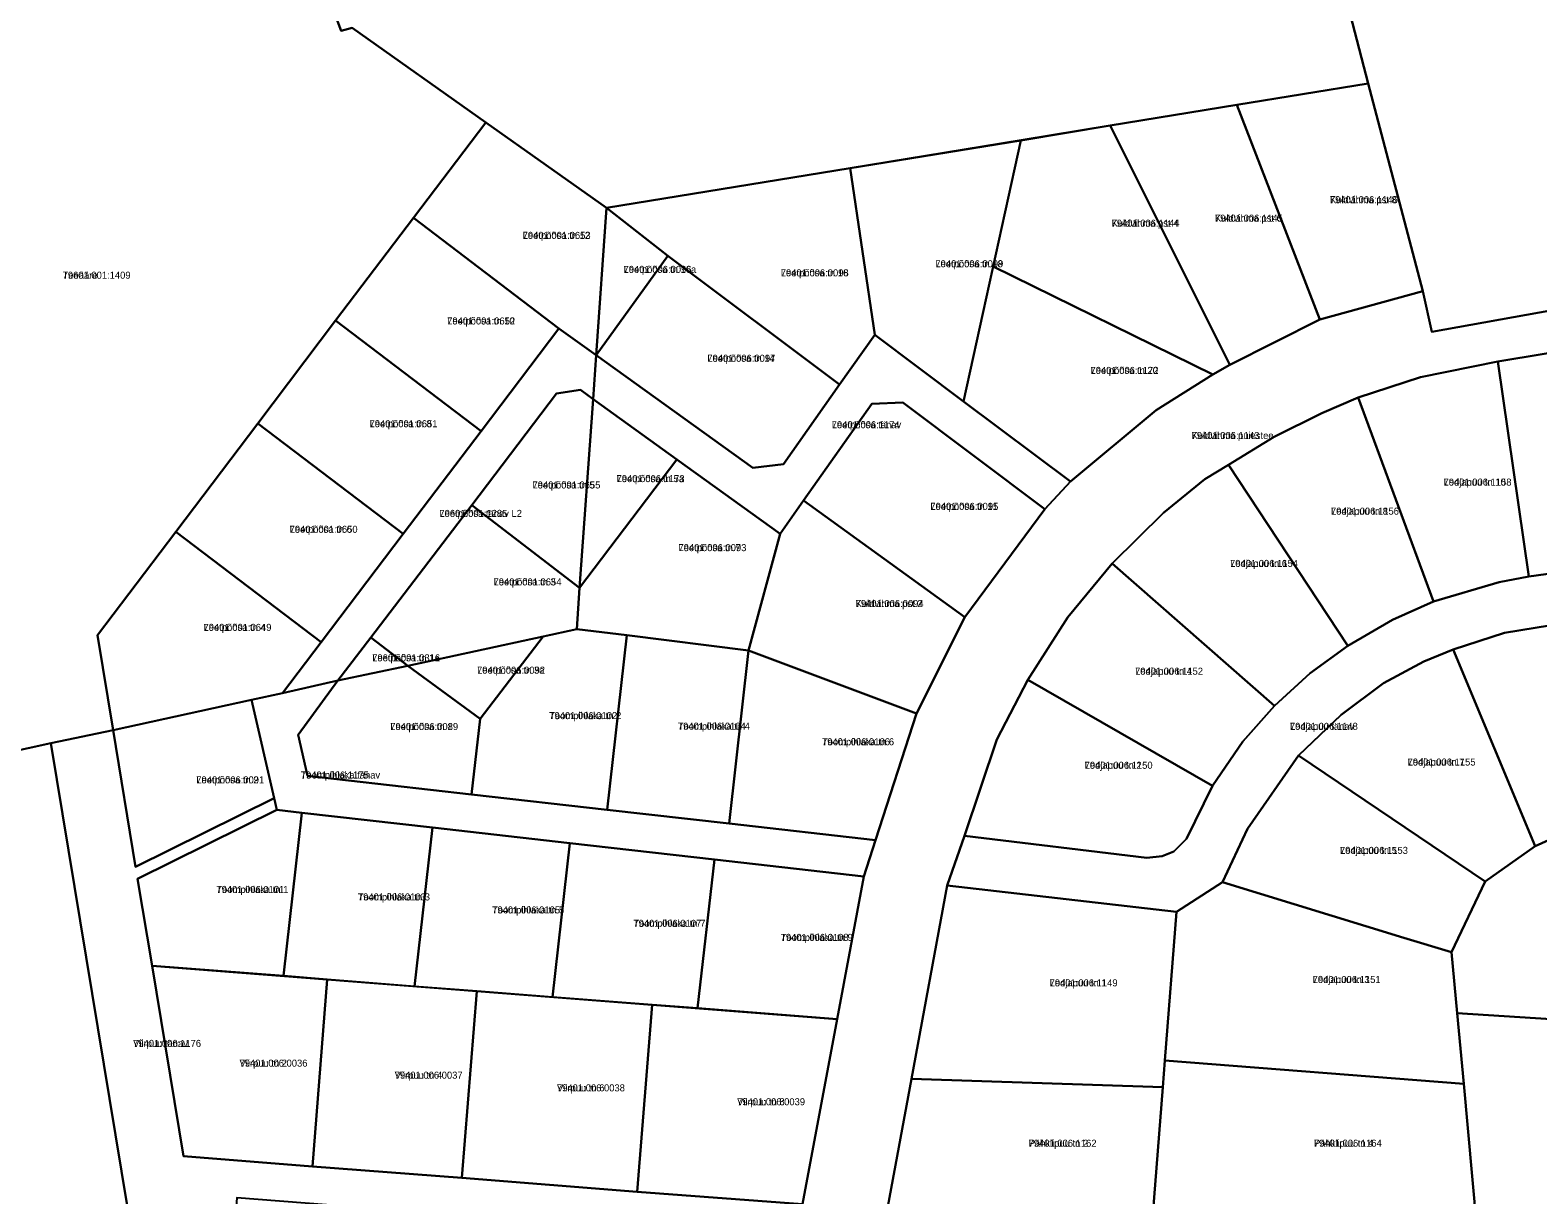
# Model space of a CAD drawing. Extents: x 625111 to 706696, y 6474150 to 6504223.
# Drawn here: x 658379.2 to 658701.1, y 6477286.7 to 6477535.3 of the extents above; entities that cross this region are included whole.
import ezdxf

# ---------------------------------------------------------------- set-up
doc = ezdxf.new("R2010")
doc.units = 0
for name, color, linetype in [('L_AADRESS', 7, 'Continuous'), ('PIIR', 7, 'Continuous'), ('TUNNUS', 7, 'Continuous')]:
    doc.layers.add(name, color=color, linetype=linetype)

msp = doc.modelspace()

# ---------------------------------------------------------------- linework, layer by layer
at = {"layer": 'PIIR'}
for points in [[(658807.19, 6477493.92), (658767, 6477486.74), (658756.55, 6477484.86), (658727.2, 6477479.64), (658678.44, 6477470.94), (658676.54, 6477479.6), (658664.87, 6477523.91), (658625, 6477677.45), (658727.35, 6477707.93), (658827.16, 6477726.6), (658855.42, 6477705.99), (658921.35, 6477514.3), (658868.14, 6477504.79)], [(658664.87, 6477523.91), (658636.85, 6477519.38), (658609.75, 6477514.92), (658590.75, 6477511.83), (658554.26, 6477505.84), (658502.28, 6477497.39), (658476.47, 6477515.58), (658447.92, 6477535.78), (658445.6, 6477535.16), (658420.4, 6477602.12), (658422.48, 6477603), (658480.42, 6477633.97), (658625, 6477677.45)], [(658295.81, 6477363.77), (658298.99, 6477419.35), (658308.47, 6477456.27), (658317.08, 6477478.52), (658327.48, 6477502.41), (658338.32, 6477525.23), (658352.68, 6477544.97), (658370, 6477564.62), (658397.69, 6477592.48), (658420.4, 6477602.12), (658445.6, 6477535.16), (658447.92, 6477535.78), (658476.47, 6477515.58), (658461.03, 6477495.21), (658444.4, 6477473.3), (658427.82, 6477451.36), (658410.32, 6477428.26), (658393.57, 6477406.17), (658396.9, 6477385.91), (658383.6, 6477383.09)], [(658664.87, 6477523.91), (658676.54, 6477479.6), (658654.55, 6477473.55), (658636.85, 6477519.38)], [(658636.85, 6477519.38), (658654.55, 6477473.55), (658635.36, 6477463.84), (658609.75, 6477514.92)], [(658461.03, 6477495.21), (658476.47, 6477515.58), (658502.28, 6477497.39), (658500.06, 6477465.93), (658492.1, 6477471.64)], [(658609.75, 6477514.92), (658635.36, 6477463.84), (658631.68, 6477461.79), (658584.8, 6477484.87), (658590.68, 6477511.77)], [(658590.68, 6477511.77), (658578.48, 6477456.07), (658559.52, 6477470.29), (658554.26, 6477505.84)], [(658554.26, 6477505.84), (658559.52, 6477470.29), (658552.02, 6477459.66), (658515.36, 6477487.16), (658502.28, 6477497.39)], [(658502.28, 6477497.39), (658515.36, 6477487.16), (658500.06, 6477465.93)], [(658475.53, 6477449.74), (658444.4, 6477473.3), (658461.03, 6477495.21), (658492.1, 6477471.64)], [(658515.36, 6477487.16), (658552.02, 6477459.66), (658540.01, 6477442.64), (658533.47, 6477441.87), (658500.06, 6477465.93)], [(658584.8, 6477484.87), (658631.68, 6477461.79), (658619.61, 6477454.18), (658601.29, 6477438.98), (658578.48, 6477456.07)], [(658458.87, 6477427.81), (658427.82, 6477451.36), (658444.4, 6477473.3), (658475.53, 6477449.74)], [(658475.53, 6477449.74), (658492.1, 6477471.64), (658500.06, 6477465.93), (658499.4, 6477456.55), (658496.67, 6477458.5), (658491.59, 6477457.72), (658473.5, 6477433.94), (658451.91, 6477405.64), (658444.92, 6477396.49), (658433.1, 6477393.78), (658441.34, 6477404.68), (658458.87, 6477427.81)], [(658500.06, 6477465.93), (658533.47, 6477441.87), (658540.01, 6477442.64), (658552.02, 6477459.66), (658559.52, 6477470.29), (658578.48, 6477456.07), (658601.29, 6477438.98), (658595.83, 6477433.06), (658565.51, 6477455.8), (658558.93, 6477455.56), (658544.34, 6477434.9), (658539.31, 6477427.79), (658517.3, 6477443.65), (658499.4, 6477456.55)], [(658725.54, 6477459.66), (658721.35, 6477419.53), (658713.41, 6477419.76), (658704.83, 6477419.45), (658699.16, 6477418.71), (658692.52, 6477464.58), (658712.34, 6477467.87), (658713.78, 6477458.02)], [(658692.52, 6477464.58), (658699.16, 6477418.71), (658692.8, 6477417.51), (658678.8, 6477413.33), (658662.76, 6477456.89), (658676.06, 6477461.21)], [(658473.5, 6477433.94), (658491.59, 6477457.72), (658496.67, 6477458.5), (658499.4, 6477456.55), (658496.52, 6477416.28)], [(658517.3, 6477443.65), (658496.52, 6477416.28), (658499.4, 6477456.55)], [(658565.51, 6477455.8), (658595.83, 6477433.06), (658578.77, 6477410.04), (658544.34, 6477434.9), (658558.93, 6477455.56)], [(658662.76, 6477456.89), (658678.8, 6477413.33), (658670.06, 6477409.44), (658660.54, 6477403.93), (658635.07, 6477442.52), (658644.77, 6477448.47), (658654.96, 6477453.55)], [(658441.34, 6477404.68), (658410.32, 6477428.26), (658427.82, 6477451.36), (658458.87, 6477427.81)], [(658517.3, 6477443.65), (658539.31, 6477427.79), (658532.6, 6477402.93), (658506.6, 6477406.15), (658495.93, 6477407.47), (658496.52, 6477416.28)], [(658635.07, 6477442.52), (658660.54, 6477403.93), (658652.51, 6477398.04), (658644.87, 6477391.12), (658610.22, 6477421.46), (658621.18, 6477432.3), (658630.02, 6477439.45)], [(658451.91, 6477405.64), (658473.5, 6477433.94), (658496.52, 6477416.28), (658495.93, 6477407.47), (658488.71, 6477405.9), (658459.87, 6477399.64)], [(658544.34, 6477434.9), (658578.77, 6477410.04), (658568.41, 6477389.45), (658532.6, 6477402.93), (658539.31, 6477427.79)], [(658396.9, 6477385.91), (658393.57, 6477406.17), (658410.32, 6477428.26), (658441.34, 6477404.68), (658433.1, 6477393.78), (658426.43, 6477392.36)], [(658610.22, 6477421.46), (658644.87, 6477391.12), (658638.1, 6477383.5), (658631.6, 6477373.99), (658592.18, 6477396.64), (658600.72, 6477409.98)], [(658495.93, 6477407.47), (658506.6, 6477406.15), (658502.38, 6477368.92), (658473.45, 6477372.2), (658475.28, 6477388.34), (658488.71, 6477405.9)], [(658720.05, 6477408.61), (658717.28, 6477368.65), (658700.53, 6477361.16), (658683.04, 6477403.08), (658693.96, 6477406.64), (658707.04, 6477408.8)], [(658459.87, 6477399.64), (658444.92, 6477396.49), (658451.91, 6477405.64)], [(658488.71, 6477405.9), (658475.28, 6477388.34), (658459.87, 6477399.64)], [(658506.6, 6477406.15), (658532.6, 6477402.93), (658528.41, 6477365.97), (658502.38, 6477368.92)], [(658532.6, 6477402.93), (658568.41, 6477389.45), (658559.69, 6477362.43), (658528.41, 6477365.97)], [(658683.04, 6477403.08), (658700.53, 6477361.16), (658689.81, 6477353.63), (658650.02, 6477380.5), (658659.08, 6477389.17), (658668.14, 6477395.9), (658676.73, 6477400.52)], [(658459.87, 6477399.64), (658475.28, 6477388.34), (658473.45, 6477372.2), (658438.41, 6477376.17), (658436.4, 6477384.89), (658444.92, 6477396.49)], [(658444.92, 6477396.49), (658436.4, 6477384.89), (658438.41, 6477376.17), (658473.45, 6477372.2), (658502.38, 6477368.92), (658528.41, 6477365.97), (658559.69, 6477362.43), (658557.17, 6477354.67), (658525.3, 6477358.28), (658494.42, 6477361.79), (658465.09, 6477365.11), (658437.21, 6477368.28), (658431.87, 6477368.87), (658431.31, 6477371.38), (658426.43, 6477392.36), (658433.1, 6477393.78)], [(658592.18, 6477396.64), (658631.6, 6477373.99), (658626.11, 6477362.68), (658623.38, 6477360.01), (658620.87, 6477359.04), (658617.58, 6477358.68), (658578.66, 6477363.32), (658585.56, 6477383.91)], [(658426.43, 6477392.36), (658431.31, 6477371.38), (658401.72, 6477356.73), (658396.9, 6477385.91)], [(658544.09, 6477284.75), (658542.61, 6477276.81), (658513.13, 6477279.07), (658490.78, 6477280.8), (658466.6, 6477282.77), (658461.61, 6477283.14), (658423.3, 6477286.06), (658420.54, 6477250.71), (658404.94, 6477253.9), (658383.6, 6477383.09), (658396.9, 6477385.91), (658401.72, 6477356.73), (658431.31, 6477371.38), (658431.87, 6477368.87), (658402.15, 6477354.15), (658405.22, 6477335.6), (658411.94, 6477294.96), (658439.5, 6477292.8), (658471.37, 6477290.37), (658508.81, 6477287.41)], [(658295.81, 6477363.77), (658383.6, 6477383.09), (658404.94, 6477253.9), (658405.39, 6477207), (658405.42, 6477203), (658367.34, 6477205.68), (658367.27, 6477249.4), (658307.44, 6477251.12)], [(658650.02, 6477380.5), (658689.81, 6477353.63), (658682.69, 6477338.5), (658672.46, 6477341.61), (658633.76, 6477353.45), (658639.09, 6477364.84)], [(658431.87, 6477368.87), (658437.21, 6477368.28), (658433.26, 6477333.44), (658405.22, 6477335.6), (658402.15, 6477354.15)], [(658700.53, 6477361.16), (658717.28, 6477368.65), (658726.84, 6477367.99), (658724.96, 6477335.12), (658724.02, 6477322.95), (658683.88, 6477325.5), (658682.69, 6477338.5), (658689.81, 6477353.63)], [(658437.21, 6477368.28), (658465.09, 6477365.11), (658461.25, 6477331.23), (658442.59, 6477332.72), (658433.26, 6477333.44)], [(658465.09, 6477365.11), (658494.42, 6477361.79), (658490.69, 6477328.94), (658474.56, 6477330.17), (658461.25, 6477331.23)], [(658494.42, 6477361.79), (658525.3, 6477358.28), (658521.7, 6477326.56), (658511.99, 6477327.31), (658490.69, 6477328.94)], [(658525.3, 6477358.28), (658557.17, 6477354.67), (658551.48, 6477324.24), (658521.7, 6477326.56)], [(658623.94, 6477347.1), (658621.46, 6477315.38), (658621.03, 6477309.71), (658567.4, 6477311.49), (658574.98, 6477352.73)], [(658623.94, 6477347.1), (658633.76, 6477353.45), (658672.46, 6477341.61), (658682.69, 6477338.5), (658683.88, 6477325.5), (658685.28, 6477310.45), (658621.46, 6477315.38)], [(658442.59, 6477332.72), (658439.5, 6477292.8), (658411.94, 6477294.96), (658405.22, 6477335.6)], [(658474.56, 6477330.17), (658471.37, 6477290.37), (658439.5, 6477292.8), (658442.59, 6477332.72)], [(658511.99, 6477327.31), (658508.81, 6477287.41), (658471.37, 6477290.37), (658474.56, 6477330.17)], [(658551.48, 6477324.24), (658544.09, 6477284.75), (658508.81, 6477287.41), (658511.99, 6477327.31)], [(658685.28, 6477310.45), (658683.88, 6477325.5), (658724.02, 6477322.95), (658723.66, 6477316.23), (658721.3, 6477278.12), (658688, 6477280.44)], [(658685.28, 6477310.45), (658688, 6477280.44), (658688.23, 6477278.64), (658653.41, 6477281.24), (658618.91, 6477282.51), (658621.03, 6477309.71), (658621.46, 6477315.38)], [(658621.03, 6477309.71), (658618.91, 6477282.51), (658562.33, 6477284.26), (658567.4, 6477311.49)]]:
    msp.add_lwpolyline(points, close=True, dxfattribs=at)
for points in [[(658544.09, 6477284.75), (658551.48, 6477324.24), (658557.17, 6477354.67), (658559.69, 6477362.43), (658568.41, 6477389.45), (658578.77, 6477410.04), (658595.83, 6477433.06), (658601.29, 6477438.98), (658619.61, 6477454.18), (658631.68, 6477461.79), (658635.36, 6477463.84), (658654.55, 6477473.55), (658676.54, 6477479.6), (658678.44, 6477470.94), (658727.2, 6477479.64)], [(658712.34, 6477467.87), (658692.52, 6477464.58), (658676.06, 6477461.21), (658662.76, 6477456.89), (658654.96, 6477453.55), (658644.77, 6477448.47), (658635.07, 6477442.52), (658630.02, 6477439.45), (658621.18, 6477432.3), (658610.22, 6477421.46), (658600.72, 6477409.98), (658592.18, 6477396.64), (658585.56, 6477383.91), (658578.66, 6477363.32), (658574.98, 6477352.73), (658567.4, 6477311.49), (658562.33, 6477284.26)], [(658707.04, 6477408.8), (658693.96, 6477406.64), (658683.04, 6477403.08), (658676.73, 6477400.52), (658668.14, 6477395.9), (658659.08, 6477389.17), (658650.02, 6477380.5), (658639.09, 6477364.84), (658633.76, 6477353.45), (658623.94, 6477347.1), (658574.98, 6477352.73), (658578.66, 6477363.32), (658617.58, 6477358.68), (658620.87, 6477359.04), (658623.38, 6477360.01), (658626.11, 6477362.68), (658631.6, 6477373.99), (658638.1, 6477383.5), (658644.87, 6477391.12), (658652.51, 6477398.04), (658660.54, 6477403.93), (658670.06, 6477409.44), (658678.8, 6477413.33), (658692.8, 6477417.51), (658699.16, 6477418.71), (658704.83, 6477419.45)]]:
    msp.add_lwpolyline(points, dxfattribs=at)

# ---------------------------------------------------------------- texts
at = {"layer": 'L_AADRESS'}
for s, p in [('Kuldvihma pst 8', (658656.7, 6477498.36)), ('Kuldvihma pst 4', (658610.08, 6477493.34)), ('Kuldvihma pst 6', (658632.15, 6477494.42)), ('Leetpõõsa tn 12', (658484.36, 6477490.75)), ('Leetpõõsa tn 16a', (658505.9, 6477483.49)), ('Leetpõõsa tn 18', (658572.47, 6477484.69)), ('Teeääre', (658386.14, 6477482.24)), ('Leetpõõsa tn 16', (658539.46, 6477482.75)), ('Leetpõõsa tn 10', (658468.24, 6477472.48)), ('Leetpõõsa tn 14', (658523.79, 6477464.52)), ('Leetpõõsa tn 20', (658605.59, 6477461.93)), ('Leetpõõsa tn 8', (658451.67, 6477450.55)), ('Leetpõõsa tänav', (658550.34, 6477450.34)), ('Kuldvihma puiestee', (658627.16, 6477448.04)), ('Leetpõõsa tn 5a', (658504.41, 6477438.83)), ('Lodjapuu tn 10', (658680.96, 6477438.09)), ('Leetpõõsa tn 5', (658486.45, 6477437.48)), ('Leetpõõsa tänav L2', (658466.58, 6477431.41)), ('Leetpõõsa tn 11', (658571.4, 6477432.92)), ('Lodjapuu tn 8', (658656.93, 6477431.89)), ('Leetpõõsa tn 6', (658434.61, 6477428.02)), ('Leetpõõsa tn 7', (658517.62, 6477424.1)), ('Lodjapuu tn 6', (658635.38, 6477420.74)), ('Leetpõõsa tn 3', (658478.14, 6477416.79)), ('Kuldvihma pst 2', (658555.45, 6477412.17)), ('Leetpõõsa tn 4', (658416.22, 6477407.09)), ('Leetpõõsa tn 1a', (658452.23, 6477400.59)), ('Leetpõõsa tn 3a', (658474.62, 6477397.96)), ('Lodjapuu tn 4', (658615.1, 6477397.73)), ('Toompihlaka tn 2', (658490.03, 6477388.25)), ('Leetpõõsa tn 1', (658456.08, 6477385.92)), ('Toompihlaka tn 4', (658517.49, 6477386)), ('Lodjapuu tänav', (658648.16, 6477385.97)), ('Toompihlaka tn 6', (658548.26, 6477382.68)), ('Lodjapuu tn 2', (658604.34, 6477377.66)), ('Lodjapuu tn 7', (658673.28, 6477378.35)), ('Leetpõõsa tn 2', (658414.68, 6477374.54)), ('Toompihlaka tänav', (658436.98, 6477375.58)), ('Lodjapuu tn 5', (658658.85, 6477359.5)), ('Toompihlaka tn 1', (658418.96, 6477351.16)), ('Toompihlaka tn 3', (658449.18, 6477349.56)), ('Toompihlaka tn 5', (658477.84, 6477346.79)), ('Toompihlaka tn 7', (658507.99, 6477343.93)), ('Toompihlaka tn 9', (658539.44, 6477340.93)), ('Lodjapuu tn 3', (658653.02, 6477331.95)), ('Lodjapuu tn 1', (658596.86, 6477331.22)), ('Viirpuu tänav', (658401.19, 6477318.31)), ('Viirpuu tn 2', (658423.91, 6477314.09)), ('Viirpuu tn 4', (658457.03, 6477311.52)), ('Viirpuu tn 6', (658491.68, 6477308.81)), ('Viirpuu tn 8', (658530.14, 6477305.85)), ('Pähklipuu tn 2', (658592.37, 6477297)), ('Pähklipuu tn 4', (658653.27, 6477297.01))]:
    msp.add_text(s, height=1.5, dxfattribs=at).set_placement(p)
at = {"layer": 'TUNNUS'}
for s, p in [('79401:006:1146', (658656.7, 6477498.36)), ('79401:006:1144', (658610.08, 6477493.34)), ('79401:006:1145', (658632.15, 6477494.42)), ('79401:001:0653', (658484.36, 6477490.75)), ('79401:006:0096', (658505.9, 6477483.49)), ('79401:006:0099', (658572.47, 6477484.69)), ('79601:001:1409', (658386.14, 6477482.24)), ('79401:006:0098', (658539.46, 6477482.75)), ('79401:001:0652', (658468.24, 6477472.48)), ('79401:006:0097', (658523.79, 6477464.52)), ('79401:006:1172', (658605.59, 6477461.93)), ('79401:001:0651', (658451.67, 6477450.55)), ('79401:006:1174', (658550.34, 6477450.34)), ('79401:006:1143', (658627.16, 6477448.04)), ('79401:006:1173', (658504.41, 6477438.83)), ('79401:006:1158', (658680.96, 6477438.09)), ('79401:001:0655', (658486.45, 6477437.48)), ('79401:006:0095', (658571.4, 6477432.92)), ('79401:006:1156', (658656.93, 6477431.89)), ('79601:001:1285', (658466.58, 6477431.41)), ('79401:001:0650', (658434.61, 6477428.02)), ('79401:006:0093', (658517.62, 6477424.1)), ('79401:006:1154', (658635.38, 6477420.74)), ('79401:001:0654', (658478.14, 6477416.79)), ('79401:006:0094', (658555.45, 6477412.17)), ('79401:001:0649', (658416.22, 6477407.09)), ('79601:001:0316', (658452.23, 6477400.59)), ('79401:006:0092', (658474.62, 6477397.96)), ('79401:006:1152', (658615.1, 6477397.73)), ('79401:006:0102', (658490.03, 6477388.25)), ('79401:006:0089', (658456.08, 6477385.92)), ('79401:006:0104', (658517.49, 6477386)), ('79401:006:1148', (658648.16, 6477385.97)), ('79401:006:0106', (658548.26, 6477382.68)), ('79401:006:1150', (658604.34, 6477377.66)), ('79401:006:1155', (658673.28, 6477378.35)), ('79401:006:0091', (658414.68, 6477374.54)), ('79401:006:1175', (658436.98, 6477375.58)), ('79401:006:1153', (658658.85, 6477359.5)), ('79401:006:0101', (658418.96, 6477351.16)), ('79401:006:0103', (658449.18, 6477349.56)), ('79401:006:0105', (658477.84, 6477346.79)), ('79401:006:0107', (658507.99, 6477343.93)), ('79401:006:0108', (658539.44, 6477340.93)), ('79401:006:1151', (658653.02, 6477331.95)), ('79401:006:1149', (658596.86, 6477331.22)), ('79401:006:1176', (658401.19, 6477318.31)), ('79401:006:0036', (658423.91, 6477314.09)), ('79401:006:0037', (658457.03, 6477311.52)), ('79401:006:0038', (658491.68, 6477308.81)), ('79401:006:0039', (658530.14, 6477305.85)), ('79401:006:1162', (658592.37, 6477297)), ('79401:006:1164', (658653.27, 6477297.01))]:
    msp.add_text(s, height=1.5, dxfattribs=at).set_placement(p)

doc.saveas('drawing.dxf')
